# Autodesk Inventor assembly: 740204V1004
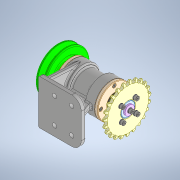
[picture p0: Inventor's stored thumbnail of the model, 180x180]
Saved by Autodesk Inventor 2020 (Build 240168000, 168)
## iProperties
Created: 2024-02
Part Number: 740204V1004
Document SubType Name: Assembly
Designer: oem
Author: oem
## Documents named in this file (18)
- C:\Users\oem\Desktop\740204V1004\740204V1004.iam
- C:\Users\oem\Desktop\740204V1004\V-벨트풀리.ipt
- C:\Users\oem\Desktop\740204V1004\가스켓.ipt
- C:\Users\oem\Desktop\740204V1004\깊은 홈 볼 베어링 6204.ipt
- C:\Users\oem\Desktop\740204V1004\본체.ipt
- C:\Users\oem\Desktop\740204V1004\스프로킷.ipt
- C:\Users\oem\Desktop\740204V1004\스프링 와셔 M5.ipt
- C:\Users\oem\Desktop\740204V1004\스프링 와셔 M10.ipt
- C:\Users\oem\Desktop\740204V1004\앤드 캡.ipt
- C:\Users\oem\Desktop\740204V1004\오일 실 20 32 5.ipt
- C:\Users\oem\Desktop\740204V1004\육각 너트 M10x1.ipt
- C:\Users\oem\Desktop\740204V1004\육각 소켓 머리 볼트 M4 x 10.ipt
- C:\Users\oem\Desktop\740204V1004\육각 소켓 머리 볼트 M5 x 12.ipt
- C:\Users\oem\Desktop\740204V1004\축.ipt
- C:\Users\oem\Desktop\740204V1004\커버.ipt
- C:\Users\oem\Desktop\740204V1004\평와셔 M10.ipt
- C:\Users\oem\Desktop\740204V1004\평행 키 5x5x12.ipt
- C:\Users\oem\Desktop\740204V1004\플랜지.ipt
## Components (4 placed, 3 different names)
1. V-벨트풀리:1 — 각도:2
2. 가스켓:1
3. 플랜지:1 — 각도:1
4. 가스켓:2
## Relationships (2: Angle 2)
- 각도:1 [Angle]: 플랜지:1
- 각도:2 [Angle]: V-벨트풀리:1
